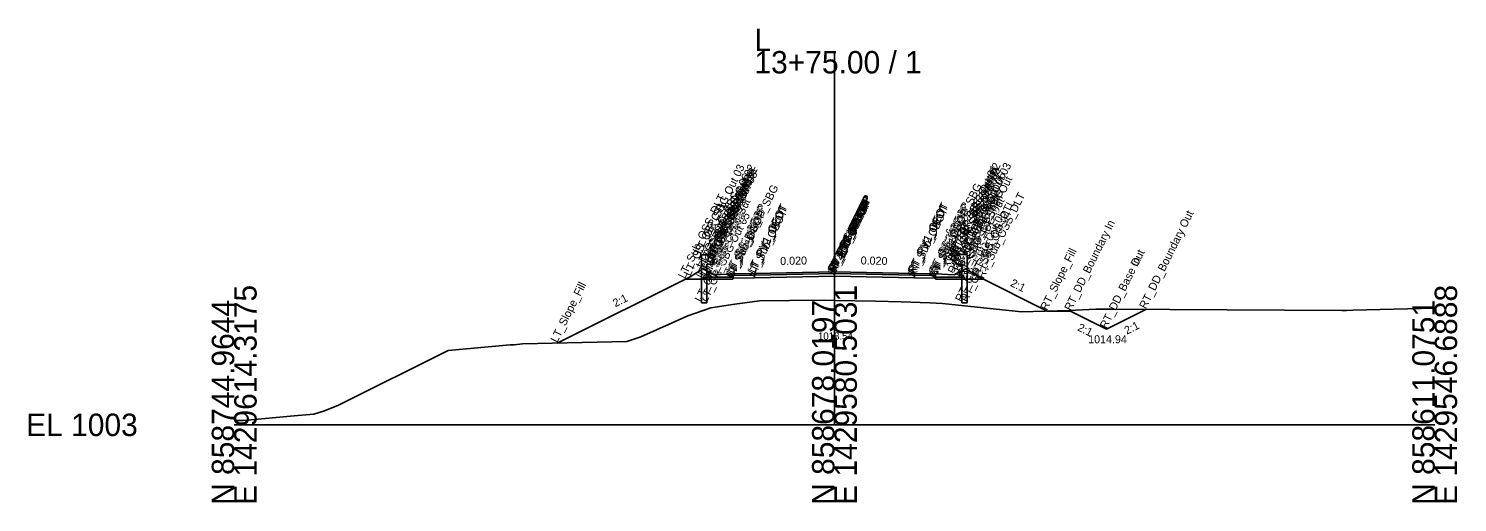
# Model space of a CAD drawing. Extents: x -26 to 153, y -10 to 13058.
# Drawn here: x -25.7 to 152.8, y 4490.3 to 4549.5 of the extents above; entities that cross this region are included whole.
import ezdxf

# ---------------------------------------------------------------- set-up
doc = ezdxf.new("R2010")
doc.units = 0
for name, color, linetype in [('Default', 7, 'Continuous'), ('Exist Cross Section Cell', 7, 'Continuous'), ('Exist XS Ground Line', 7, 'Continuous'), ('Old_Level_50', 7, 'Continuous'), ('Prop CMT Conc Surface', 7, 'Continuous'), ('Prop CMT Concrete Structures', 7, 'Continuous'), ('Prop CMT Ditch DDE', 7, 'Continuous'), ('Prop CMT Guardrail SBG', 7, 'Continuous'), ('Prop CMT Pvmt Course 1', 7, 'Continuous'), ('Prop CMT Pvmt Course 2', 7, 'Continuous'), ('Prop CMT Pvmt Course SBG', 7, 'Continuous'), ('Prop CMT Pvmt Surface', 7, 'Continuous'), ('Prop CMT Pvmt Surface Shoulder', 7, 'Continuous'), ('Prop CMT Shld Paved Course 1', 7, 'Continuous'), ('Prop CMT Shld Paved Course 2', 7, 'Continuous'), ('Prop CMT Slope Grass', 7, 'Continuous'), ('Prop CMT Subgrade Daylight Point', 7, 'Continuous'), ('Prop CMT Subgrade Earthwork', 7, 'Continuous'), ('Prop XS Ditch Slope Text', 7, 'Continuous'), ('Prop XS Ditch Standard Text', 7, 'Continuous'), ('Prop XS Dump Level', 7, 'Continuous'), ('Prop XS Hydro Elevations', 7, 'Continuous'), ('Prop XS SE Text', 7, 'Continuous'), ('Prop XS Side Slope Text', 7, 'Continuous')]:
    doc.layers.add(name, color=color, linetype=linetype)

msp = doc.modelspace()

# ---------------------------------------------------------------- linework, layer by layer
at = {"layer": 'Exist Cross Section Cell'}
for p, q in [((75, 4500), (75, 4546.7)), ((0, 4500), (75, 4500)), ((75, 4500), (150, 4500))]:
    msp.add_line(p, q, dxfattribs=at)
at = {"layer": 'Exist XS Ground Line'}
msp.add_lwpolyline([(0, 4500.56), (1.18, 4500.54), (7.93, 4501.16), (9.97, 4501.35), (11.27, 4501.76), (13.05, 4502.45), (26.75, 4509.29), (34.47, 4509.98), (34.98, 4510.01), (36.03, 4510.1), (49.06, 4510.42), (50.82, 4510.99), (56.7, 4513.61), (59.56, 4514.62), (62.54, 4515.08), (65.64, 4515.49), (69.39, 4515.54), (73.72, 4515.57), (75, 4515.54), (80.14, 4515.43), (83.32, 4515.38), (86.93, 4515.25), (88.52, 4515.14), (98.36, 4514.13), (104.28, 4514.3), (107.65, 4514.43), (109.74, 4514.43), (138.38, 4514.29), (139, 4514.3), (139.79, 4514.33), (150, 4514.57)], dxfattribs=at)
at = {"layer": 'Old_Level_50'}
for p, q in [((109, 4511.94), (113.92, 4514.41)), ((113.92, 4514.41), (109.74, 4514.43))]:
    msp.add_line(p, q, dxfattribs=at)
for points in [[(109.74, 4514.43), (107.65, 4514.43), (104.28, 4514.3), (101.56, 4514.22)], [(101.56, 4514.22), (104.56, 4514.16), (109, 4511.94)]]:
    msp.add_lwpolyline(points, dxfattribs=at)
at = {"layer": 'Prop CMT Conc Surface'}
for points in [[(62.31, 4518.85), (59.98, 4518.75), (59.31, 4519.1)], [(87.64, 4518.85), (89.97, 4518.76), (90.64, 4519.1)]]:
    msp.add_lwpolyline(points, dxfattribs=at)
at = {"layer": 'Prop CMT Concrete Structures'}
for points in [[(62.31, 4518.85), (59.98, 4518.75), (59.31, 4519.1)], [(59.31, 4519.1), (59.31, 4518.43)], [(62.31, 4518.43), (62.31, 4518.85)], [(87.64, 4518.85), (89.97, 4518.76), (90.64, 4519.1)], [(87.64, 4518.43), (87.64, 4518.85)], [(90.64, 4519.1), (90.64, 4518.43)], [(59.31, 4518.43), (62.31, 4518.43)], [(90.64, 4518.43), (87.64, 4518.43)]]:
    msp.add_lwpolyline(points, dxfattribs=at)
at = {"layer": 'Prop CMT Ditch DDE'}
for points in [[(101.56, 4514.22), (104.56, 4514.16), (109, 4511.94)], [(109, 4511.94), (113.92, 4514.41)], [(109, 4511.94), (109, 4511.94)]]:
    msp.add_lwpolyline(points, dxfattribs=at)
at = {"layer": 'Prop CMT Guardrail SBG'}
for points in [[(58.37, 4515.25), (58.37, 4521.25)], [(58.37, 4521.25), (59.71, 4521.25), (59.98, 4520.96)], [(59.98, 4520.96), (59.71, 4520.67)], [(59.71, 4520.67), (59.98, 4520.38)], [(91.58, 4521.26), (90.24, 4521.26), (89.97, 4520.96)], [(89.97, 4520.96), (90.24, 4520.67)], [(90.24, 4520.67), (89.97, 4520.38)], [(91.58, 4515.26), (91.58, 4521.26)], [(59.98, 4520.38), (59.71, 4520.09), (59.04, 4520.09)], [(59.04, 4520.09), (59.04, 4515.25)], [(89.97, 4520.38), (90.24, 4520.09), (90.91, 4520.09)], [(90.91, 4520.09), (90.91, 4515.26)], [(59.04, 4515.25), (58.37, 4515.25)], [(90.91, 4515.26), (91.58, 4515.26)]]:
    msp.add_lwpolyline(points, dxfattribs=at)
at = {"layer": 'Prop CMT Pvmt Course 1'}
for points in [[(75, 4519.1), (65, 4518.9)], [(65, 4518.9), (65, 4518.69)], [(65, 4518.69), (75, 4518.89)], [(75, 4518.89), (75, 4519.1)], [(75, 4519.1), (85, 4518.9)], [(75, 4518.89), (75, 4519.1)], [(85, 4518.69), (75, 4518.89)], [(85, 4518.9), (85, 4518.69)]]:
    msp.add_lwpolyline(points, dxfattribs=at)
msp.add_lwpolyline([(75, 4518.89), (75, 4518.98), (75, 4518.98), (75, 4518.89)], close=True, dxfattribs=at)
msp.add_lwpolyline([(75, 4518.89), (75, 4518.98), (75, 4518.98), (75, 4518.89)], close=True, dxfattribs=at)
at = {"layer": 'Prop CMT Pvmt Course 2'}
for points in [[(75, 4518.89), (65, 4518.69)], [(65, 4518.69), (65, 4518.36)], [(75, 4518.56), (75, 4518.89)], [(75, 4518.56), (75, 4518.89)], [(75, 4518.89), (85, 4518.69)], [(85, 4518.69), (85, 4518.36)], [(65, 4518.36), (75, 4518.56)], [(85, 4518.36), (75, 4518.56)]]:
    msp.add_lwpolyline(points, dxfattribs=at)
at = {"layer": 'Prop CMT Pvmt Course SBG'}
for points in [[(62.31, 4518.43), (59.31, 4518.43), (58.81, 4518.43), (58.56, 4518.18)], [(58.56, 4518.18), (62.31, 4518.18)], [(62.31, 4518.18), (62.31, 4518.43)], [(87.64, 4518.18), (87.64, 4518.43)], [(87.64, 4518.43), (90.64, 4518.43), (91.14, 4518.43), (91.39, 4518.18)], [(91.39, 4518.18), (87.64, 4518.18)]]:
    msp.add_lwpolyline(points, dxfattribs=at)
at = {"layer": 'Prop CMT Pvmt Surface'}
for points in [[(75, 4519.1), (65, 4518.9)], [(75, 4519.1), (85, 4518.9)]]:
    msp.add_lwpolyline(points, dxfattribs=at)
at = {"layer": 'Prop CMT Pvmt Surface Shoulder'}
for points in [[(65, 4518.9), (62.31, 4518.85)], [(85, 4518.9), (87.64, 4518.85)]]:
    msp.add_lwpolyline(points, dxfattribs=at)
at = {"layer": 'Prop CMT Shld Paved Course 1'}
for points in [[(65, 4518.9), (62.31, 4518.85)], [(62.31, 4518.85), (62.31, 4518.64)], [(62.31, 4518.64), (65, 4518.69)], [(65, 4518.69), (65, 4518.9)], [(85, 4518.9), (87.64, 4518.85)], [(85, 4518.69), (85, 4518.9)], [(87.64, 4518.64), (85, 4518.69)], [(87.64, 4518.85), (87.64, 4518.64)]]:
    msp.add_lwpolyline(points, dxfattribs=at)
at = {"layer": 'Prop CMT Shld Paved Course 2'}
for points in [[(65, 4518.69), (62.31, 4518.64)], [(65, 4518.36), (65, 4518.69)], [(85, 4518.69), (87.64, 4518.64)], [(85, 4518.36), (85, 4518.69)], [(62.31, 4518.64), (62.31, 4518.43), (62.31, 4518.31)], [(62.31, 4518.31), (65, 4518.36)], [(87.64, 4518.31), (85, 4518.36)], [(87.64, 4518.64), (87.64, 4518.43), (87.64, 4518.31)]]:
    msp.add_lwpolyline(points, dxfattribs=at)
at = {"layer": 'Prop CMT Slope Grass'}
for points in [[(59.31, 4519.1), (58.54, 4519.49), (56.98, 4518.51), (40.36, 4510.2)], [(90.64, 4519.1), (91.41, 4519.5), (92.97, 4518.52), (101.56, 4514.22)]]:
    msp.add_lwpolyline(points, dxfattribs=at)
at = {"layer": 'Prop CMT Subgrade Earthwork'}
for points in [[(62.31, 4518.18), (58.56, 4518.18), (56.31, 4518.18)], [(65, 4518.36), (62.31, 4518.31)], [(62.31, 4518.31), (62.31, 4518.18)], [(75, 4518.56), (65, 4518.36)], [(75, 4518.56), (85, 4518.36)], [(85, 4518.36), (87.64, 4518.31)], [(87.64, 4518.31), (87.64, 4518.18)], [(87.64, 4518.18), (91.39, 4518.18), (93.64, 4518.18)]]:
    msp.add_lwpolyline(points, dxfattribs=at)

# ---------------------------------------------------------------- texts
at = {"layer": 'Default'}
msp.add_text('-', height=0.0001, dxfattribs=at).set_placement((0, 4500))
at = {"layer": 'Exist Cross Section Cell'}
for s, p in [('L', (65, 4546.7)), ('13+75.00 / 1', (65, 4543.9)), ('EL 1003', (-26, 4498.6))]:
    msp.add_text(s, height=2.8, dxfattribs=at).set_placement(p)
for s, p in [('E 1429614.3175', (2.8, 4490)), ('E 1429580.5031', (77.8, 4490)), ('E 1429546.6888', (152.8, 4490)), ('N 858744.9644', (0, 4490)), ('N 858678.0197', (75, 4490)), ('N 858611.0751', (150, 4490))]:
    msp.add_text(s, height=2.8, rotation=90, dxfattribs=at).set_placement(p)
at = {"layer": 'Prop CMT Subgrade Daylight Point'}
msp.add_text('1018.54', height=0.9, dxfattribs=at).set_placement((72.94, 4510.64))
at = {"layer": 'Prop XS Ditch Slope Text'}
for rotation, p in [(333.4349, (105.28, 4511.84)), (26.5651, (111.53, 4511.26))]:
    msp.add_text('2:1', height=1, rotation=rotation, dxfattribs=at).set_placement(p)
at = {"layer": 'Prop XS Ditch Standard Text'}
msp.add_text('1014.94', height=1, dxfattribs=at).set_placement((106.7, 4510.19))
at = {"layer": 'Prop XS Dump Level'}
for s, p in [('LT_GR_SBG Out 03', (58.37, 4521.25)), ('LT_GR_SBG Out 06', (59.04, 4520.09)), ('LT_GR_SBG Out 02', (59.71, 4521.25)), ('LT_GR_SBG Out 09', (59.71, 4520.67)), ('LT_GR_SBG Out 07', (59.71, 4520.09)), ('LT_GR_SBG Out 01', (59.98, 4520.96)), ('LT_GR_SBG Out 08', (59.98, 4520.38)), ('RT_GR_SBG Out 01', (89.97, 4520.96)), ('RT_GR_SBG Out 08', (89.97, 4520.38)), ('RT_GR_SBG Out 02', (90.24, 4521.26)), ('RT_GR_SBG Out 09', (90.24, 4520.67)), ('RT_GR_SBG Out 07', (90.24, 4520.09)), ('RT_GR_SBG Out 06', (90.91, 4520.09)), ('RT_GR_SBG Out 03', (91.58, 4521.26)), ('LT_SBG_C1 Shelf Out', (58.81, 4518.43)), ('LT_Sub_OEOP_SBG', (62.31, 4518.18)), ('RT_Sub_OEOP_SBG', (87.64, 4518.18)), ('RT_CG_Top_BOC', (90.64, 4519.1)), ('RT_SBG_C1 Shelf Out', (91.14, 4518.43)), ('LT_Sub_OSS_DLT', (56.31, 4518.18)), ('LT_GS_OS_CTL', (56.98, 4518.51)), ('LT_GS_OS_SBG', (58.54, 4519.49)), ('LT_Sub_SBG Out', (58.56, 4518.18)), ('LT_CG_Top_BOC', (59.31, 4519.1)), ('LT_CG_Bot_BOC', (59.31, 4518.43)), ('LT_CG_Top_Gut', (59.98, 4518.75)), ('LT_PS1_OEOP', (62.31, 4518.85)), ('LT_PV1_OEOT', (65, 4518.9)), ('RT_PV1_OEEOP', (75, 4518.98)), ('RT_PV2_OEEOP', (75, 4518.89)), ('LT_PV1_OEEOP', (75, 4518.98)), ('LT_PV2_OEEOP', (75, 4518.89)), ('RT_Sub_OEEOP', (75, 4518.56)), ('RT_PV1_IEEOP', (75, 4518.98)), ('RT_PV2_IEEOP', (75, 4518.89)), ('LT_Sub_OEEOP', (75, 4518.56)), ('LT_PV1_IEEOP', (75, 4518.98)), ('LT_PV2_IEEOP', (75, 4518.89)), ('RT_PV1_OEOT', (85, 4518.9)), ('RT_PV2_OEOT', (85, 4518.69)), ('RT_PS1_OEOP', (87.64, 4518.85)), ('RT_PS2_OEOP', (87.64, 4518.64)), ('RT_CG_Top_Gut', (89.97, 4518.76)), ('RT_CG_Bot_BOC', (90.64, 4518.43)), ('RT_Sub_SBG Out', (91.39, 4518.18)), ('RT_GS_OS_SBG', (91.41, 4519.5)), ('RT_GS_OS_CTL', (92.97, 4518.52)), ('RT_Sub_OSS_DLT', (93.64, 4518.18)), ('LT_GR_SBG Out 04', (58.37, 4515.25)), ('LT_GR_SBG Out 05', (59.04, 4515.25)), ('LT_PS2_OEOP', (62.31, 4518.64)), ('LT_Sub_OEOP', (62.31, 4518.31)), ('LT_CG_Bot_IE', (62.31, 4518.43)), ('LT_PV2_OEOT', (65, 4518.69)), ('LT_Sub_OEOT', (65, 4518.36)), ('RT_Sub_OEOT', (85, 4518.36)), ('RT_Sub_OEOP', (87.64, 4518.31)), ('RT_CG_Bot_IE', (87.64, 4518.43)), ('RT_GR_SBG Out 05', (90.91, 4515.26)), ('RT_GR_SBG Out 04', (91.58, 4515.26)), ('RT_DD_Boundary Out', (113.92, 4514.41)), ('PV1_PGL', (75, 4519.1)), ('PV2_PGL', (75, 4518.89)), ('RT_DD_Boundary In', (104.56, 4514.16)), ('RT_Slope_Fill', (101.56, 4514.22)), ('RT_DD_Base Out', (109, 4511.94)), ('RT_DD_Base In', (109, 4511.94)), ('LT_Slope_Fill', (40.36, 4510.2))]:
    msp.add_text(s, height=1, rotation=63.5833, dxfattribs=at).set_placement(p)
at = {"layer": 'Prop XS Hydro Elevations'}
for s, p in [('1021.75', (60.98, 4519.75)), ('1021.76', (89.97, 4519.76))]:
    msp.add_text(s, height=1, rotation=90, dxfattribs=at).set_placement(p)
at = {"layer": 'Prop XS SE Text'}
for rotation, p in [(1.1458, (68.23, 4519.97)), (358.8542, (78.27, 4520.04))]:
    msp.add_text('0.020', height=1, rotation=rotation, dxfattribs=at).set_placement(p)
at = {"layer": 'Prop XS Side Slope Text'}
for rotation, p in [(333.4349, (96.89, 4517.39)), (26.5651, (47.62, 4514.68))]:
    msp.add_text('2:1', height=1, rotation=rotation, dxfattribs=at).set_placement(p)

doc.saveas('drawing.dxf')
